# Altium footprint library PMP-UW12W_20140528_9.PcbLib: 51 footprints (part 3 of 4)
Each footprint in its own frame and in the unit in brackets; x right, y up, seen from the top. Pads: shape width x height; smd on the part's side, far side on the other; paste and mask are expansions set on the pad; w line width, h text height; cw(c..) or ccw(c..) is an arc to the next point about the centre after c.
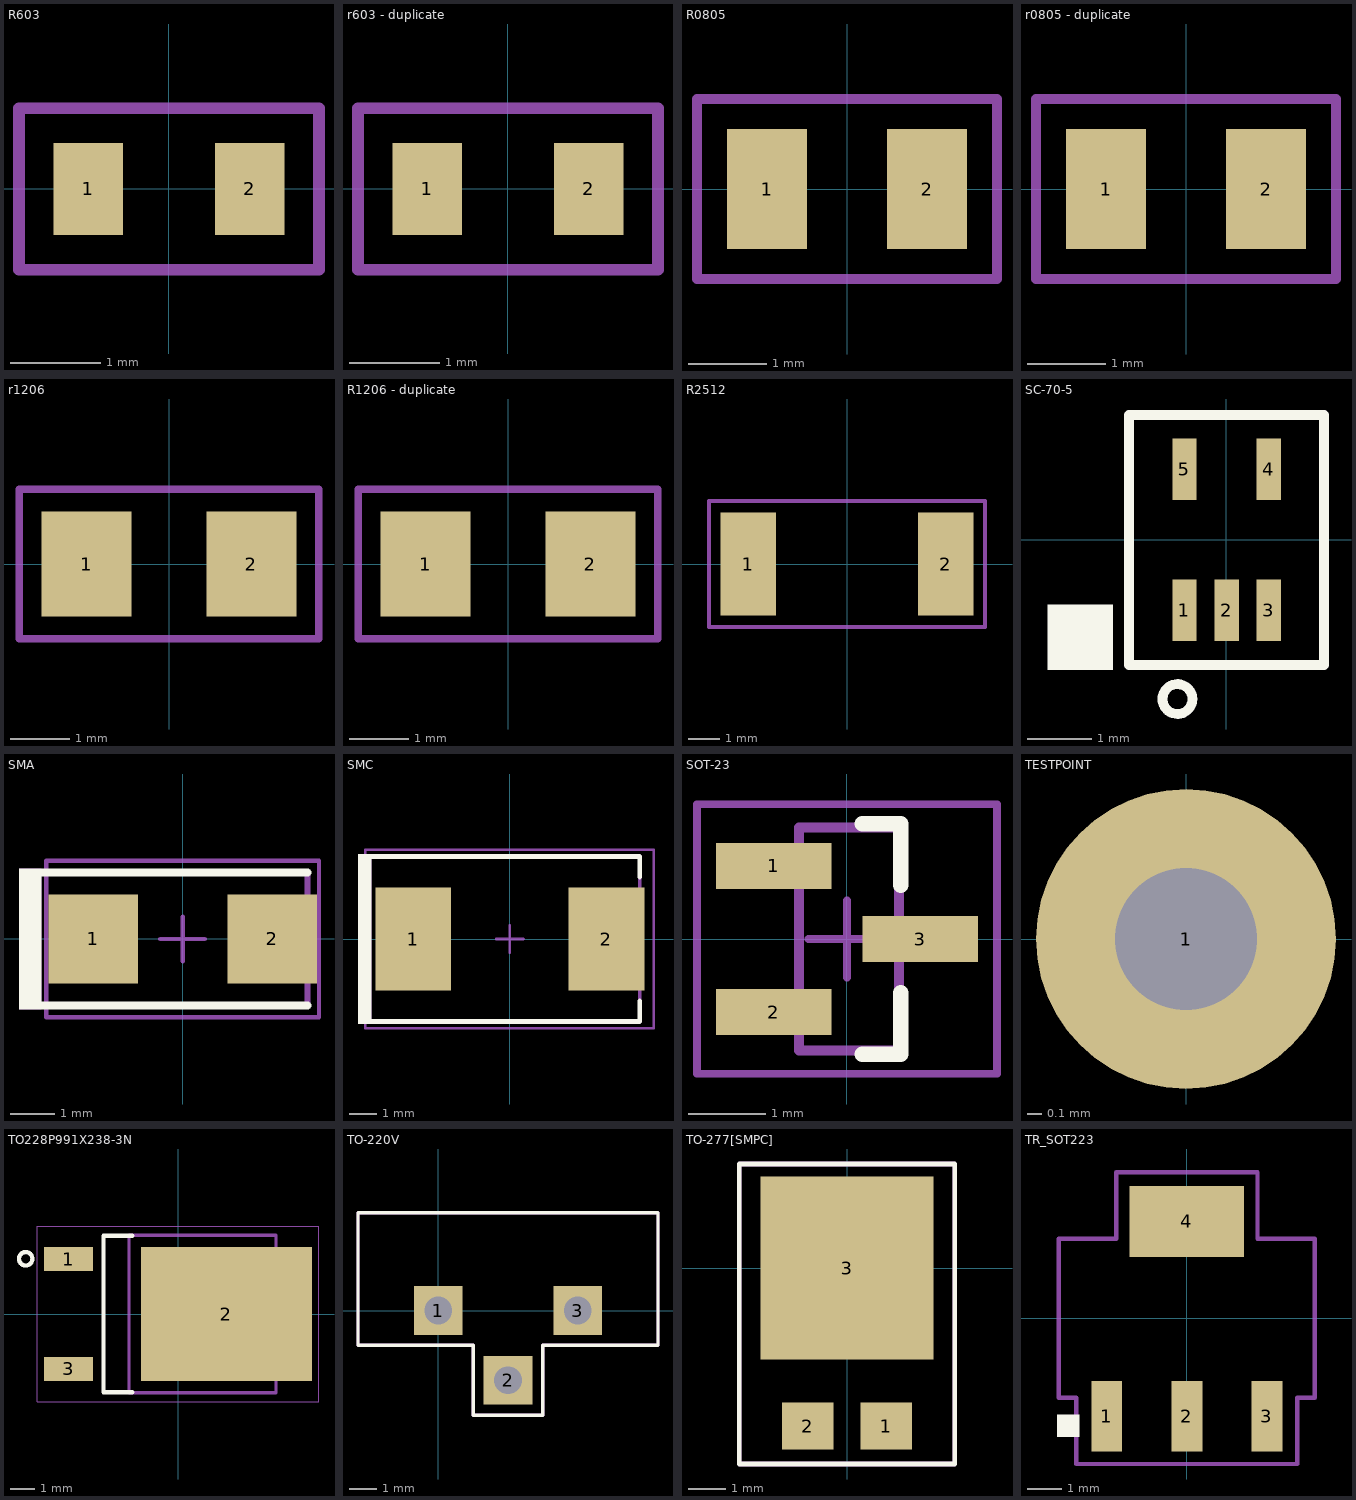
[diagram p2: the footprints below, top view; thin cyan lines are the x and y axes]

## R603 [mil]
pads (2):
  rect 30x40 smd: 1(-35,0) 2(35,0)
Mechanical 5:
  lines w5: -65,-35 -65,35 65,35 65,-35 -65,-35
  text ".Designator" at 260,25 h60

## r603 - duplicate [mil]
pads (2):
  rect 30x40 smd: 1(-35,0) 2(35,0)
Mechanical 5:
  lines w5: -65,-35 65,-35 65,35 -65,35 -65,-35
  text ".Designator" at 260,25 h60

## R0805 [mil]
pads (2):
  rect 40x60 smd: 1(-40,0) 2(40,0)
Mechanical 5:
  lines w5: -75,-45 -75,45 75,45 75,-45 -75,-45
  text ".Designator" at 5,60 h60

## r0805 - duplicate [mil]
pads (2):
  rect 40x60 smd: 1(-40,0) 2(40,0)
Mechanical 5:
  lines w5: -75,-45 -75,45 75,45 75,-45 -75,-45
  text ".Designator" at 5,60 h60

## r1206 [mil]
pads (2):
  rect 60x70 smd: 1(-55,0) 2(55,0)
Mechanical 5:
  lines w5: -100,-50 100,-50 100,50 -100,50 -100,-50
  text ".Designator" at 80,-80 h60

## R1206 - duplicate [mil]
pads (2):
  rect 60x70 smd: 1(-55,0) 2(55,0)
Mechanical 5:
  lines w5: -100,-50 100,-50 100,50 -100,50 -100,-50
  text ".Designator" at 80,-80 h60

## R2512 [mil]
pads (2):
  rect 70x130 smd: 1(-125,0) 2(125,0)
Mechanical 5:
  lines w5: -175,-80 175,-80 175,80 -175,80 -175,-80
  text ".Designator" at 65,-110 h60

## SC-70-5 [mil]
pads (5):
  rect 15x38 smd: 1(-25.9,-43.4) 2(0.1,-43.4) 3(26.1,-43.4) 4(26.1,43.6) 5(-25.9,43.6)
Top Overlay:
  circle w6: c-30.22,-98 r9.22
  region: -110,-80 -70,-80 -70,-40 -110,-40
  lines w6: -60,-77 60,-77 60,77 -60,77 -60,-77
Mechanical 5:
  lines w5: -59.9,-77.4 -59.9,77.6 60.1,77.6 60.1,-77.4 -59.9,-77.4
  text "*" at -50,-80 h25
  text ".Designator" at -103,-12 h60

## SMA [mm] "Molded Diode, 2-Leads, Body 4.3x2.6mm, IPC Medium Density, based on OnSemi component dimensions and land pattern"
height 2.27
pads (2):
  rect 2x2 smd: 1(-2,0) 2(2,0)
Top Overlay:
  rectangle: -3.658,-1.575 -3.15,1.575
  lines w0.178: -3.327,-1.486 2.794,-1.486 ; -3.327,1.486 2.794,1.486
Mechanical 5:
  rectangle: -3.658,-1.575 -3.15,1.575
  lines w0.127: -3.327,-1.486 2.794,-1.486 2.794,1.486 -3.327,1.486
  text ".Designator" at -2.769,-0.33 h1.02
Mechanical 15:
  lines w0.1: -0.5,0 0.5,0 ; 0,-0.5 0,0.5 ; -3.05,-1.75 -3.05,1.75 3.05,1.75 3.05,-1.75 -3.05,-1.75
3D body: height 2.42, standoff 0.02, extent -2.6,-1.3 2.6,1.3

## SMC [mil] "Molded Diode, 2-Leads, Body 6.9x5.8mm, IPC Medium Density, based on OnSemi component dimensions and land patterns"
height 94.88
pads (2):
  rect 110x150 smd: 1(-140.49,0) 2(140.49,0)
Top Overlay:
  rectangle: -221,-123.5 -201,123.5
  lines w7: -210,-120 189,-120 189,-90.25 ; -210,120 189,120 189,90.25
Mechanical 5:
  rectangle: -221,-123.5 -201,123.5
  lines w5: -210,-120 189,-120 189,120 -210,120
  text ".Designator" at -85,-20 h40
Mechanical 15:
  lines w3.94: -19.69,0 19.68,0 ; 0,-19.68 0,19.68 ; -210.46,-129.92 -210.46,129.92 209.38,129.92 209.38,-129.92 -210.46,-129.92
3D body: height 91.35, standoff 0.6, extent -156.49,-116.14 156.5,116.15

## SOT-23 [mm] "SOT23, 3-Leads, Body 2.9x1.3mm, Pitch 0.95mm, Lead Span 2.5mm, IPC Medium Density"
height 1.1
pads (3):
  rect 1.5x0.6 smd: 1(-0.95,0.95) 2(-0.95,-0.95) 3(0.95,0)
Top Overlay:
  lines w0.2: 0.2,-1.5 0.7,-1.5 0.7,-0.7 ; 0.2,1.5 0.7,1.5 0.7,0.7
Mechanical 5:
  lines w0.127: -1.16,-1.15 -0.625,-1.15 -0.625,-1.45 0.675,-1.45 0.675,-0.2 1.21,-0.2 1.21,0.2 0.675,0.2 0.675,1.45 -0.625,1.45 -0.625,1.15 -1.16,1.15 -1.16,0.75 -0.625,0.75 -0.625,-0.75 -1.16,-0.75 -1.16,-1.15
  text ".Designator" at -0.175,1.225 h0.64
Mechanical 15:
  lines w0.1: -0.5,0 0.5,0 ; 0,-0.5 0,0.5 ; -1.95,-1.75 -1.95,1.75 1.95,1.75 1.95,-1.75 -1.95,-1.75
3D body: height 1, standoff 0, extent -1.16,-1.45 1.21,1.45

## TESTPOINT [mil]
height 314.96
pads (1):
  round 80 hole 37.99: 1(0,0)

## TO228P991X238-3N [mm] "IC, MOSFET N-CH, 500V, 200MA, DPAK"
height 2.38
pads (3):
  rect 2.05x1 smd: 1(-4.55,2.28) 3(-4.55,-2.28)
  rect 7.1x5.55 smd: 2(2,0)
Top Overlay:
  circle w0.178: c-6.326,2.291 r0.279
  lines w0.178: -1.9,-3.25 -3.1,-3.25 -3.1,3.25 -1.9,3.25
  text ".Designator" at -1.524,4 h1.02
Top Paste:
  region: -0.96,-2.02 0.64,-2.02 0.64,-0.38 -0.96,-0.38
  region: 1.2,-2.02 2.8,-2.02 2.8,-0.38 1.2,-0.38
  region: 3.36,-2.02 4.96,-2.02 4.96,-0.38 3.36,-0.38
  region: -0.96,0.38 0.64,0.38 0.64,2.02 -0.96,2.02
  region: 1.2,0.38 2.8,0.38 2.8,2.02 1.2,2.02
  region: 3.36,0.38 4.96,0.38 4.96,2.02 3.36,2.02
Mechanical 5:
  circle w0.127: c-6.326,2.291 r0.279
  lines w0.127: 4.065,-2.668 4.359,-2.668 4.955,-2.006 4.955,2.006 4.359,2.668 4.065,2.668 ; -2.03,-3.27 -2.03,3.27 4.065,3.27 4.065,-3.27 -2.03,-3.27
  text ".Designator" at -1.524,-0.508 h1.02
Mechanical 15:
  lines w0.05: -5.85,-3.65 5.85,-3.65 5.85,3.65 -5.85,3.65 -5.85,-3.65
Mechanical 16:
  circle w0.05: c0,0 r0.35
  lines w0.05: -0.5,0 0.5,0 ; 0,-0.5 0,0.5
3D body: height 2.38, standoff 0, extent -2.03,-3.27 4.065,3.27

## TO-220V [mil]
pads (3):
  rect 70x70 hole 40: 1(0,0) 2(100,-100) 3(200,0)
Top Overlay:
  lines w5: -115,-50 50,-50 50,-150 150,-150 150,-50 315,-50 315,140 -115,140 -115,-50
Mechanical 5:
  lines w5: -115,-50 -115,140 315,140 315,-50 150,-50 150,-150 50,-150 50,-50 -115,-50
  text ".Designator" at -9.25,-88.9 h60

## TO-277[SMPC] [mil]
pads (3):
  rect 55x50 smd: 1(42,-168.6) 2(-42,-168.6)
  rect 185x195 smd: 3(0,0)
Top Overlay:
  lines w5: -115,-209 -115,111 115,111 115,-209 -115,-209
Mechanical 5:
  lines w5: -115,-209 115,-209 115,111 -115,111 -115,-209
  text ".Designator" at 165,-130 h60

## TR_SOT223 [mil]
pads (4):
  rect 35x80 smd: 1(-90.6,-110.9) 2(0,-110.9) 3(90.6,-110.9)
  rect 130x80 smd: 4(0,109.5)
Top Overlay:
  region: -146.8,-134.2 -146.8,-109.2 -121.8,-109.2 -121.8,-134.2
  region: -146.8,-134.2 -146.8,-109.2 -121.8,-109.2 -121.8,-134.2
Mechanical 5:
  lines w5: -145,-90 -145,90 -80,90 -80,165 80,165 80,90 145,90 145,-90 125,-90 125,-165 -125,-165 -125,-90 -145,-90
  text ".Designator" at 190,45 h60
